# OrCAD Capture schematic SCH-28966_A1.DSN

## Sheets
1 1. Title Page: title: BRKT-STBC-SA9500; rev: A1; company: Freescale Semiconductor; note: SCH-28966 PDF: SPF-28966; note: 6501 William Cannon Drive West; note: Austin, TX 78735-8598
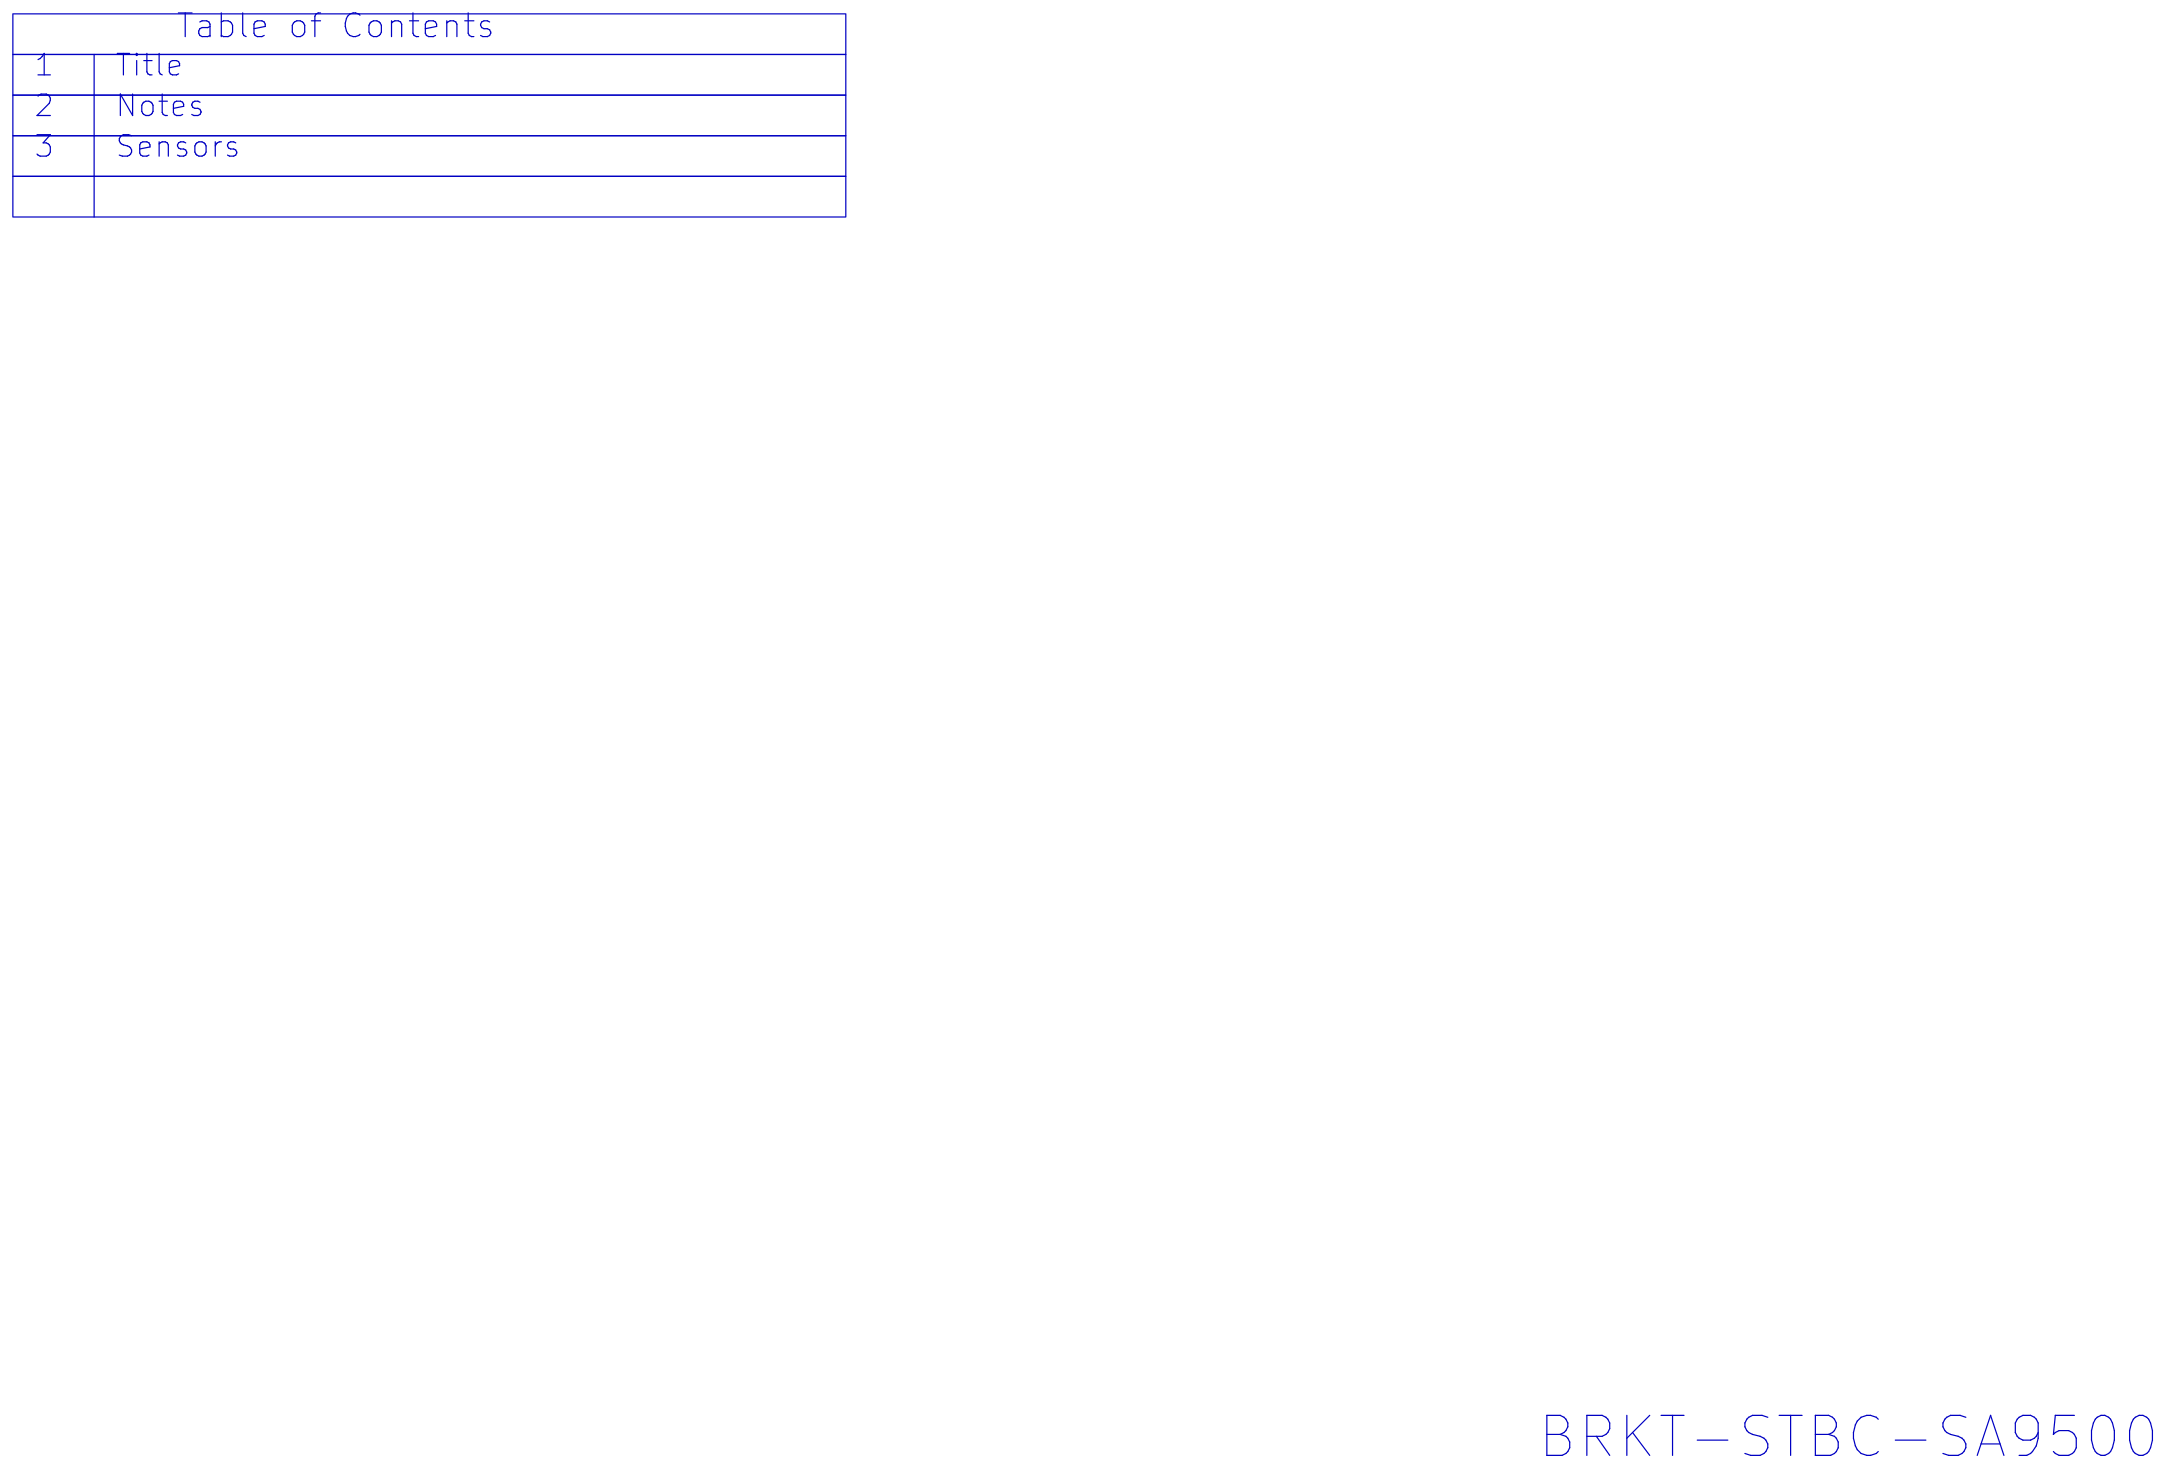
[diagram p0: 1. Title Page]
2 2. Notes: note: 2100 E Elliot Rd; note: Tempe, AZ 85284
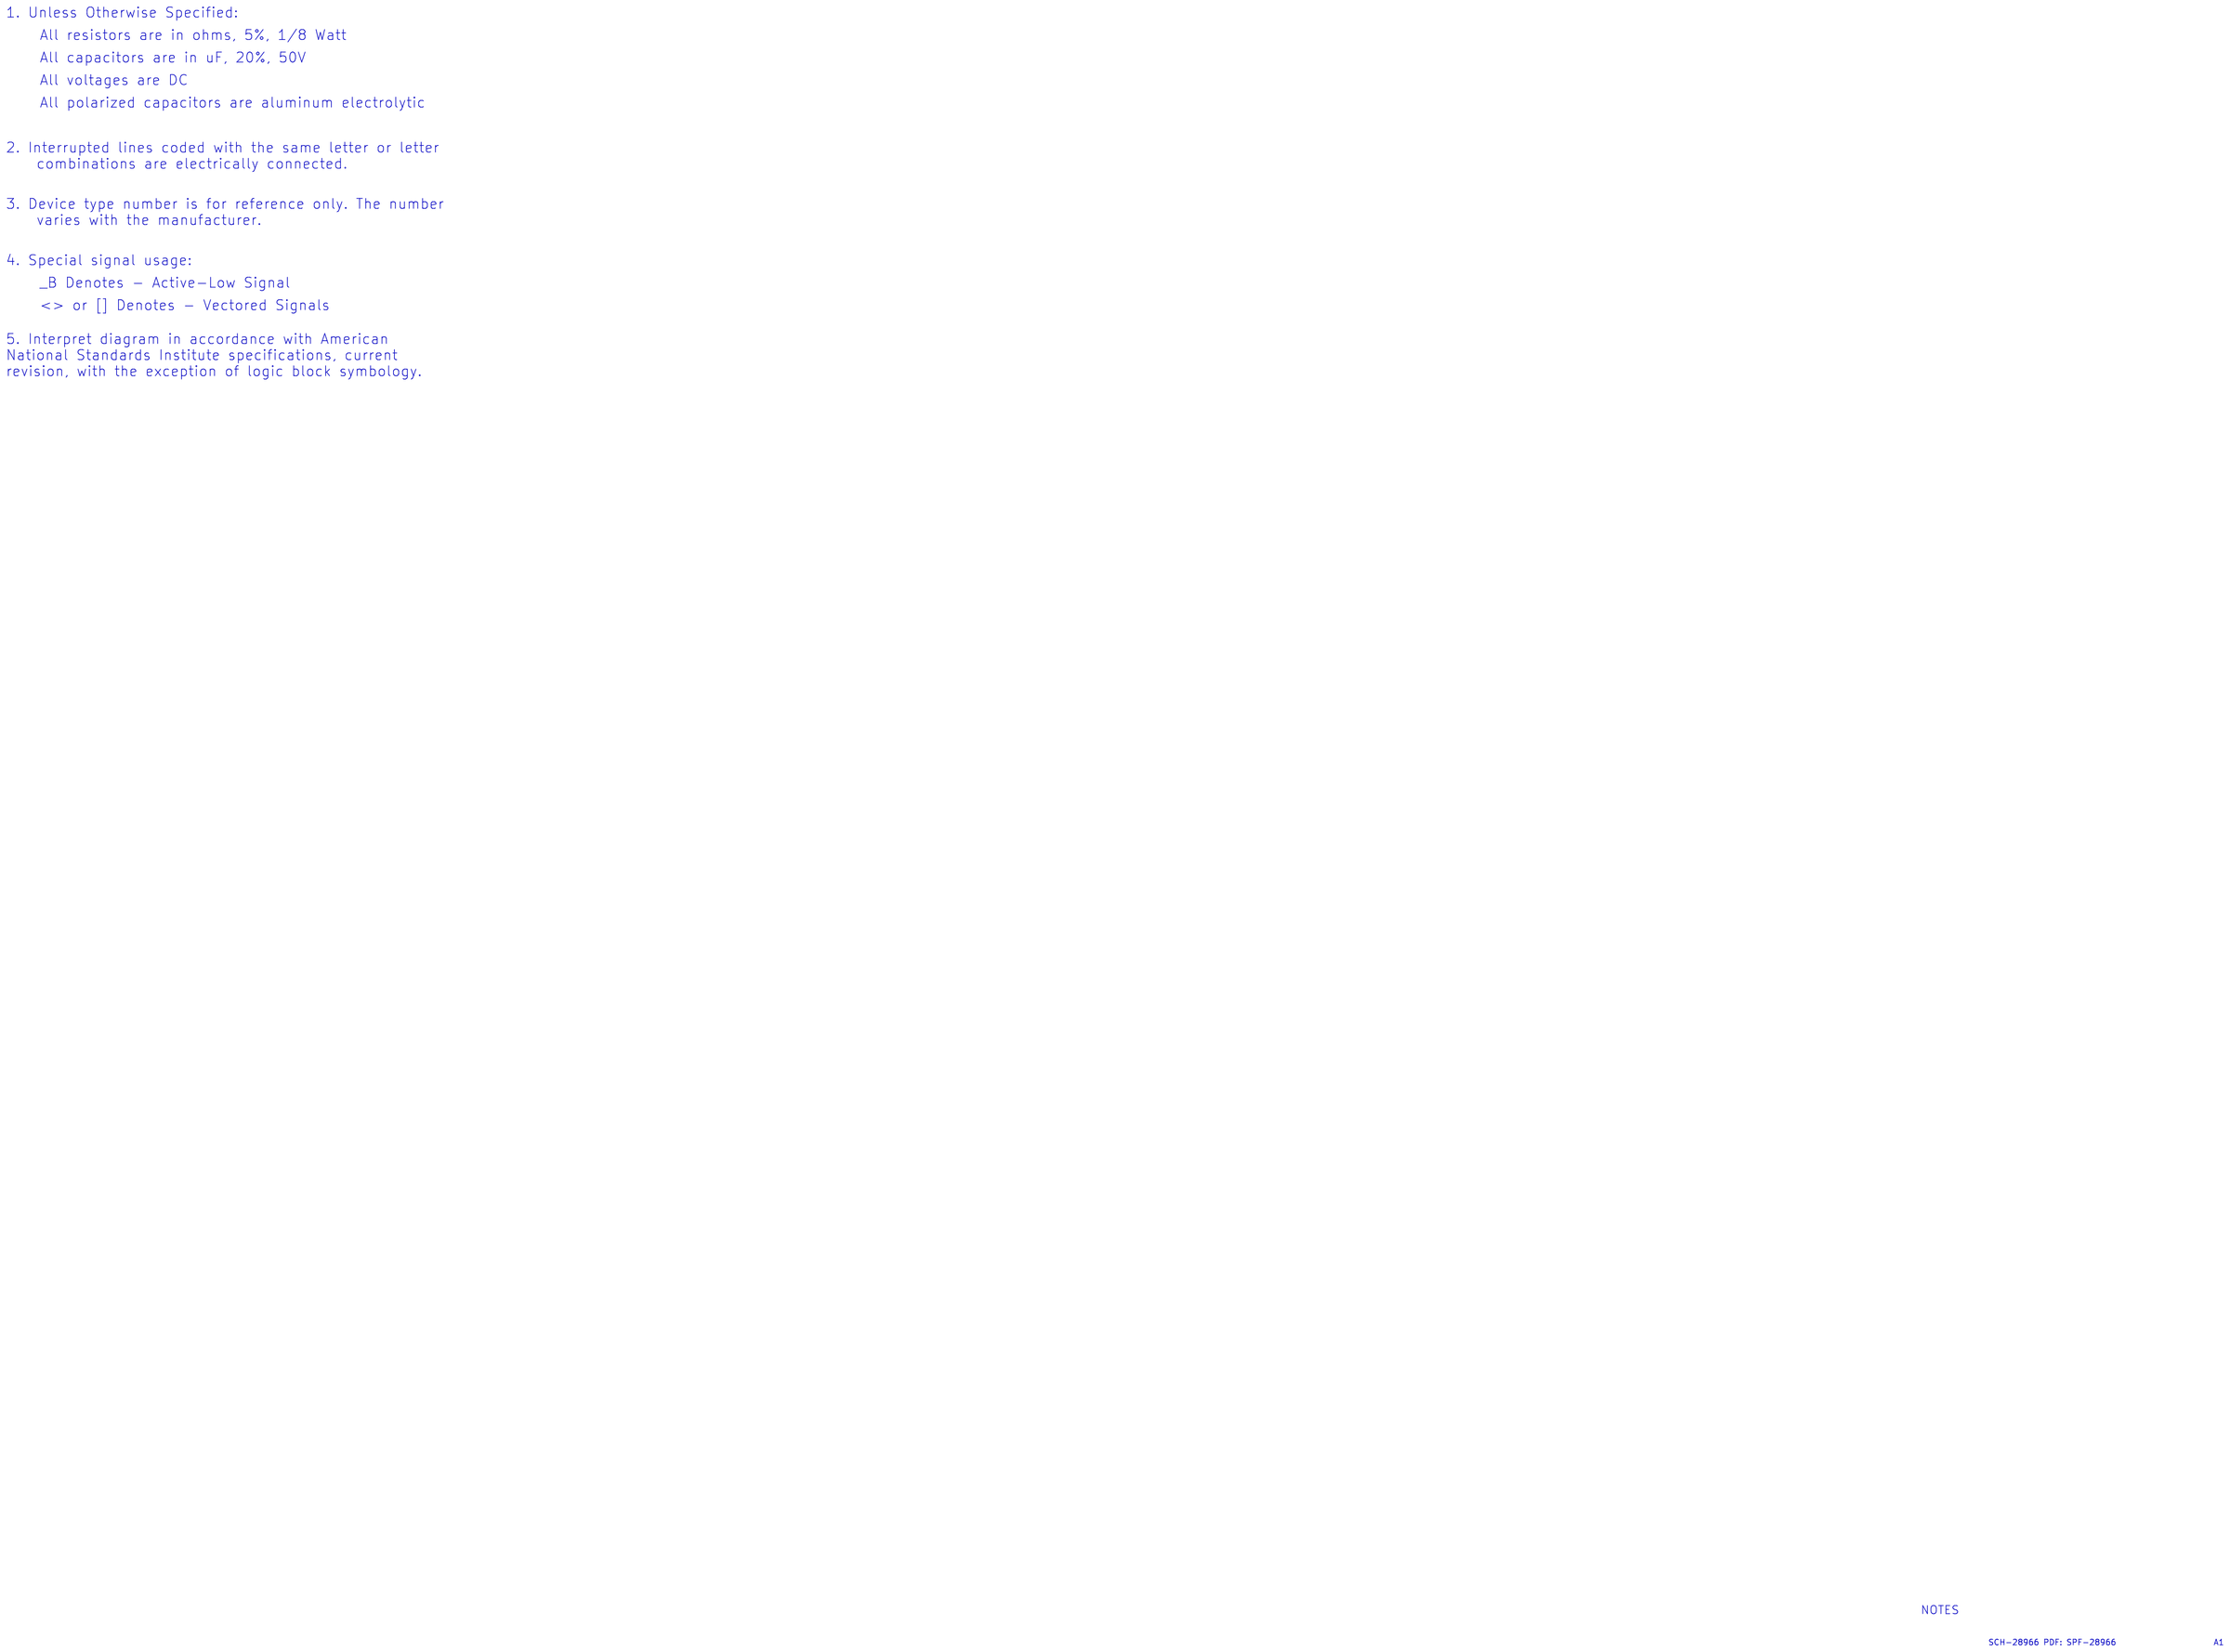
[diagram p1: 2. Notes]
3 3. Sensors: size C; note: 2100 E Elliot Rd; note: Tempe, AZ 85284
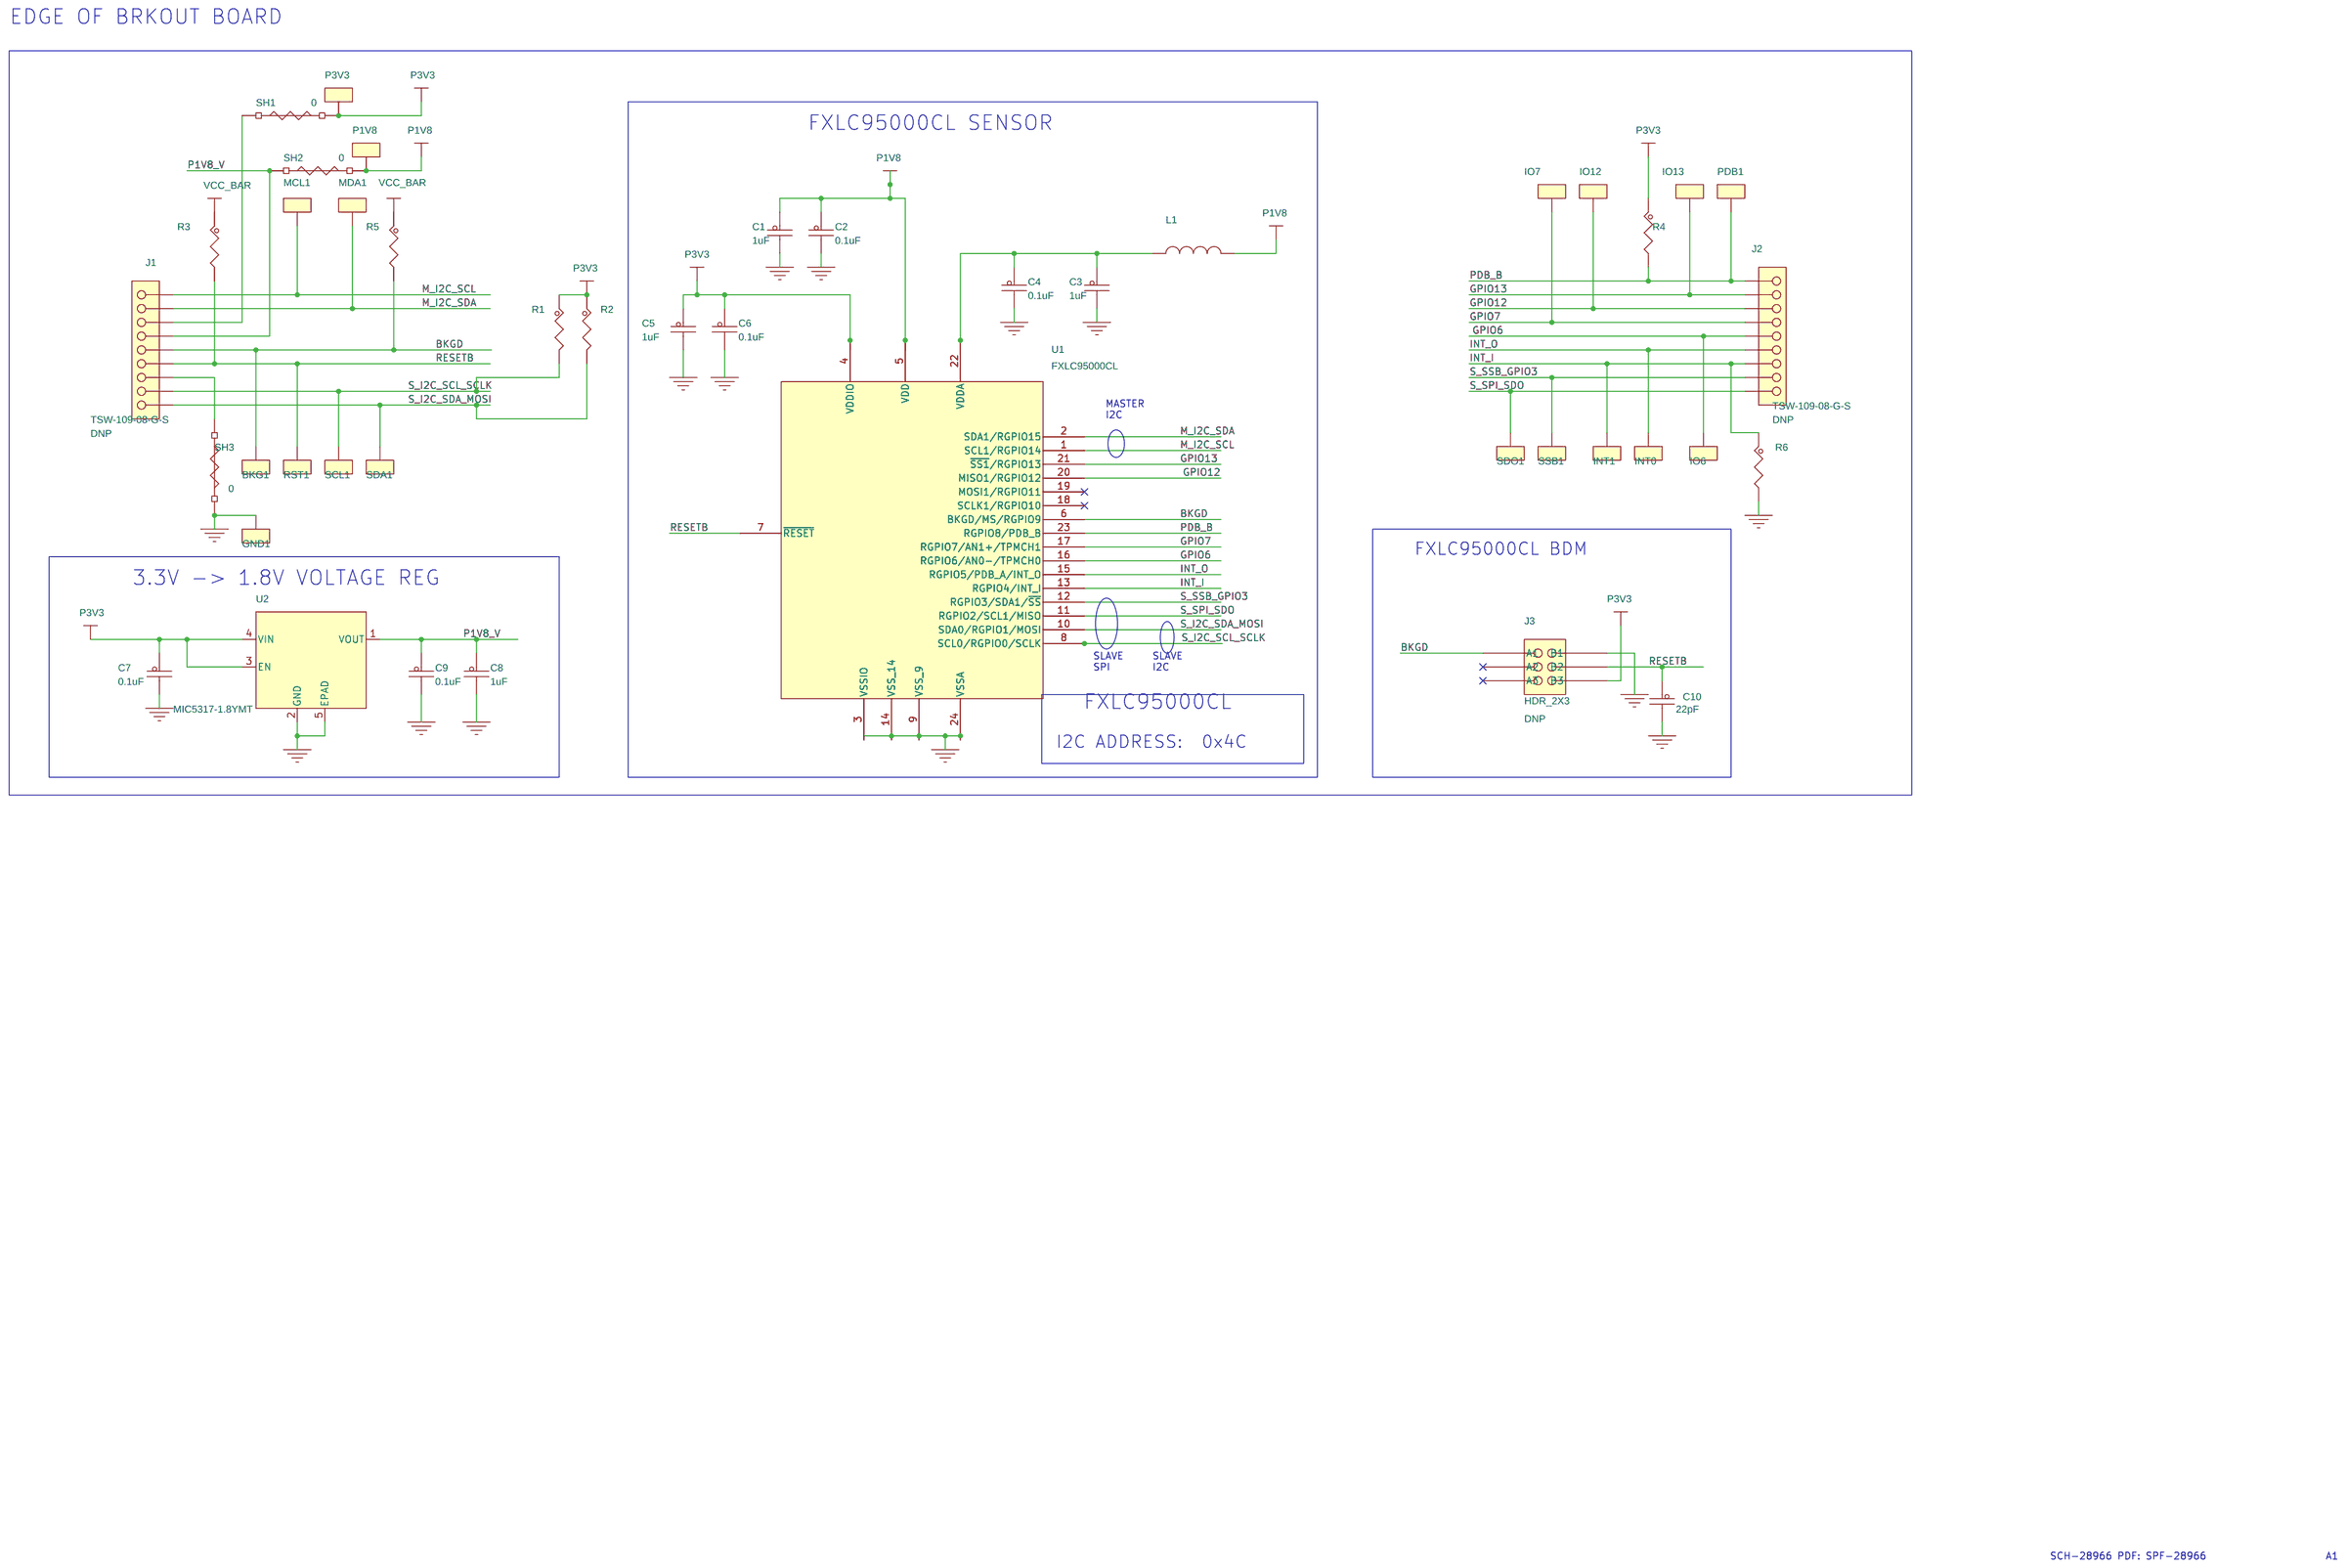
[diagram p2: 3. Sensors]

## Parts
BKG1  0805  [testpoint_122x049mil]
C1  1uF  [CC0402_25]
C2  0.1uF  [CC0402_25]
C3  1uF  [CC0402_25]
C4  0.1uF  [CC0402_25]
C5  1uF  [CC0402_25]
C6  0.1uF  [CC0402_25]
C7  0.1uF  [CC0402_25]
C8  1uF  [CC0402_25]
C9  0.1uF  [CC0402_25]
C10  22pF  [CC0402_25]
GND1  0805  [testpoint_122x049mil]
INT0  0805  [testpoint_122x049mil]
INT1  0805  [testpoint_122x049mil]
IO6  0805  [testpoint_122x049mil]
IO7  0805  [testpoint_122x049mil]
IO12  0805  [testpoint_122x049mil]
IO13  0805  [testpoint_122x049mil]
J1  TSW-109-08-G-S  [hdr9_2p54_3x23]
J2  TSW-109-08-G-S  [hdr9_2p54_3x23]
J3  HDR_2X3  [HDR203_TMM_SM]
L1  600OHM  [IND_0603]
MCL1  0805  [testpoint_122x049mil]
MDA1  0805  [testpoint_122x049mil]
P1V8  0805  [testpoint_122x049mil]
P3V3  0805  [testpoint_122x049mil]
PDB1  0805  [testpoint_122x049mil]
R1  4.7K  [RC0603]
R2  4.7K  [RC0603]
R3  4.7K  [RC0603]
R4  10K  [RC0603]
R5  1K  [RC0603]
R6  4.7K  [RC0603]
RST1  0805  [testpoint_122x049mil]
SCL1  0805  [testpoint_122x049mil]
SDA1  0805  [testpoint_122x049mil]
SDO1  0805  [testpoint_122x049mil]
SH1  0  [SH0201]
SH2  0  [SH0201]
SH3  0  [SH0201]
SSB1  0805  [testpoint_122x049mil]
U1  FXLC95000CL  [LGA24_0P5_3X5]
U2  MIC5317-1.8YMT  [tdfn5_1p05x1p05mm]

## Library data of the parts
BKG1 GND1 INT0 INT1 IO6 IO7 IO12 IO13 MCL1 MDA1 P1V8 P3V3 PDB1 RST1 SCL1 SDA1 SDO1 SSB1 = TEST_POINT: TEST POINT PAD 3.1MMX1.25MM SMT AEC-Q200 0805; AGILE_PN: 211-79608; CAD_APPROVED: Yes; HEIGHT: 1.45MM; MFG_NAME01: KOA Speer; MFG_PN01: RCTCTE; ROHS: Yes
C1 C3 C5 C8 = CAP_NP: CAP CER 1uF 16V 10% X5R 0402; AGILE_PN: 150-78973; CAD_APPROVED: Yes; FPLIST: CC0402_25,CC0402_HD,0402_CC; HEIGHT: 0.55 MM; MFG_NAME01: WALSIN TECHNOLOGY CORP.; MFG_PN01: 0402X105K160CT; ROHS: Yes; TOL: 10%; Tolerance: 10%; VOLTAGE: 16V
C2 C4 C6 C7 C9 = CAP_NP: CAP CER 0.1uF 50V 10% X7R 0402; AGILE_PN: 150-79069; CAD_APPROVED: Yes; FPLIST: CC0402_25,CC0402_HD,0402_CC; HEIGHT: 0.55MM; MFG_NAME01: MURATA; MFG_PN01: GRM155R71H104KE14D; ROHS: Yes; TOL: 10%; Tolerance: 10%; VOLTAGE: 50V
C10 = CAP_NP: CAP CER 22pF 50V 5% C0G AEC-Q200 0402; AGILE_PN: 150-79024; CAD_APPROVED: Yes; FPLIST: CC0402_25,CC0402_HD,0402_CC; HEIGHT: 0.55MM; MFG_NAME01: MURATA; MFG_PN01: GCM1555C1H220JA16; ROHS: Yes; Tolerance: 5%; VOLTAGE: 50V
J1 J2 = CON_HDR_1X9: HDR 1X9 TH 100MIL SP 343H AU 200L; AGILE_PN: 210-79902; ASSY_OPT: DNP; CAD_APPROVED: Yes; HEIGHT: 8.71MM; MFG_NAME01: SAMTEC; ROHS: Yes
J3 = CONN_HDR_3X2: HDR 2X3 SMT 78.7MIL SP 240H SN LOPRO; AGILE_PN: 211-75111; ASSY_OPT: DNP; CAD_APPROVED: Yes; HEIGHT: 6.096MM; MFG_NAME01: SAMTEC; MFG_PN01: TMM-103-01-T-D-SM; ROHS: Yes
L1 = INDUCTOR: IND 600 OHM@100MHZ 0.2A 25% 0603 SMT; AGILE_PN: 180-75046; CAD_APPROVED: Yes; FPLIST: IND_0603,0603_CC; HEIGHT: 0.95MM; MFG_NAME01: MURATA; MFG_PN01: BLM18BD601SN1D; PART_TYPE: FERRITE; ROHS: Yes
R1-R3 R6 = RES: RES MF 4.7K 1/10W 5% 0603; AGILE_PN: 470-75414; CAD_APPROVED: Yes; FPLIST: RC0603_OV,RC0603,0603_CC; HEIGHT: 0.55 MM; MFG_NAME01: VISHAY INTERTECHNOLOGY; MFG_PN01: CRCW06034K70JNEA; ROHS: Yes; Tolerance: 5%
R4 = RES: RES MF 10K 1/10W 5% 0603; AGILE_PN: 470-75410; CAD_APPROVED: Yes; FPLIST: RC0603_OV,RC0603,0603_CC; HEIGHT: 0.55MM; MFG_NAME01: KOA SPEER; MFG_PN01: RK73B1JTTD103J; ROHS: Yes; Tolerance: 5%
R5 = RES: RES MF 1.0K 1/10W 5% 0603; AGILE_PN: 470-75412; CAD_APPROVED: YES; FPLIST: RC0603_OV,RC0603,0603_CC; HEIGHT: 0.6MM; MFG_NAME01: VENKEL COMPANY; MFG_PN01: CR0603-10W-102JT; ROHS: Yes; Tolerance: 5%
SH1-SH3 = RES_SHORT-2: ZERO OHM CUT TRACE 0201 PADS; NO PART TO ORDER; AGILE_PN: 470-76473; CAD_APPROVED: Yes; FPLIST: SH0201,SH0201_CC; HEIGHT: 0.1 MM; MFG_NAME01: LAYOUT ELEMENT ONLY; MFG_PN01: LAYOUT ELEMENT ONLY; ROHS: Yes
U1 = MXLC9560C_24P: IC ACCELEROMETER SENSOR 3-AXIS 2G/4G/8G 1.72-3.6V LGA24; AGILE_PN: 315-79475; CAD_APPROVED: Yes; HEIGHT: 1.1MM; MFG_NAME01: FREESCALE SEMICONDUCTOR; MFG_PN01: FXLC95000CLR1; ROHS: Yes
U2 = MIC5317_TDFN5P: IC VREG LDO 1.8V 0.15A 2.5-6V TDFN4; AGILE_PN: 315-80593; CAD_APPROVED: Yes; HEIGHT: 0.6MM; MFG_NAME01: MICREL; MFG_PN01: MIC5317-1.8YMT TZ; ROHS: Yes

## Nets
GND: C1.2 C2.2 C3.2 C4.2 C5.2 C6.2 C7.2 C8.2 C9.2 C10.2 GND1.1 J3.2(B1) R6.2 SH3.2 U1.3(VSSIO) U1.9(VSS) U1.14(VSS) U1.24(VSSA) U2.2(GND) U2.5(EPAD)
P1V8: C1.1 C2.1 L1.2 P1V8.1 SH2.2 U1.5(VDD)
P1V8_V: C8.1 C9.1 J1.4 SH2.1 U2.1(VOUT)
P3V3: C5.1 C6.1 C7.1 J3.6(B3) P3V3.1 R1.1 R2.1 R3.1 R4.1 R5.1 SH1.2 U1.4(VDDIO) U2.3(EN) U2.4(VIN)
BKGD: BKG1.1 J1.5 J3.1(A1) R5.2 U1.6(BKGD/MS/RGPIO9)
GPIO6: IO6.1 J2.5 U1.16(RGPIO6/AN0-/TPMCH0)
GPIO7: IO7.1 J2.4 U1.17(RGPIO7/AN1+/TPMCH1)
GPIO12: IO12.1 J2.3 U1.20(MISO1/RGPIO12)
GPIO13: IO13.1 J2.2 U1.21(~{SS1}/RGPIO13)
INT_I: INT1.1 J2.7 R6.1 U1.13(RGPIO4/INT_I)
INT_O: INT0.1 J2.6 U1.15(RGPIO5/PDB_A/INT_O)
M_I2C_SCL: J1.1 MCL1.1 U1.1(SCL1/RGPIO14)
M_I2C_SDA: J1.2 MDA1.1 U1.2(SDA1/RGPIO15)
PDB_B: J2.1 PDB1.1 R4.2 U1.23(RGPIO8/PDB_B)
RESETB: C10.1 J1.6 J3.4(B2) R3.2 RST1.1 U1.7(~{RESET})
S_I2C_SCL_SCLK: J1.8 R1.2 SCL1.1 U1.8(SCL0/RGPIO0/SCLK)
S_I2C_SDA_MOSI: J1.9 R2.2 SDA1.1 U1.10(SDA0/RGPIO1/MOSI)
S_SPI_SDO: J2.9 SDO1.1 U1.11(RGPIO2/SCL1/MISO)
S_SSB_GPIO3: J2.8 SSB1.1 U1.12(RGPIO3/SDA1/~{SS})
N20846695: C3.1 C4.1 L1.1 U1.22(VDDA)
N20846720: J1.3 SH1.1
N20846848: J1.7 SH3.1

Not connected (* = marked no-connect by the designer): J3 3(A2)* 5(A3)*; U1 18(SCLK1/RGPIO10)* 19(MOSI1/RGPIO11)*

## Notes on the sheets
sheet 1
- Table of Contents
- 1
- Title
- 2
- Notes
- 3
- Sensors
- BRKT-STBC-SA9500
sheet 2
- 1. Unless Otherwise Specified:
- All resistors are in ohms, 5%, 1/8 Watt
- All capacitors are in uF, 20%, 50V
- All voltages are DC
- All polarized capacitors are aluminum electrolytic
- 2. Interrupted lines coded with the same letter or letter
      combinations are electrically connected.
- 3. Device type number is for reference only. The number
      varies with the manufacturer.
- 4. Special signal usage:
- _B Denotes - Active-Low Signal
- <> or [] Denotes - Vectored Signals
- 5. Interpret diagram in accordance with American
  National Standards Institute specifications, current
  revision, with the exception of logic block symbology.
- NOTES
- SCH-28966 PDF: SPF-28966
- A1
sheet 3
- EDGE OF BRKOUT BOARD
- FXLC95000CL SENSOR
- MASTER
  I2C
- FXLC95000CL BDM
- 3.3V -> 1.8V VOLTAGE REG
- SLAVE
  SPI
- SLAVE
  I2C
- FXLC95000CL
- I2C ADDRESS:  0x4C
- SCH-28966 PDF: SPF-28966
- A1
